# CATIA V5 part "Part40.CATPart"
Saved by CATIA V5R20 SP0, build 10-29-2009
Part number: FA 168700-1
Revision: ANY
Definition: UNKNOWN
Nomenclature: FA 168700-1
Source: Unknown
Bounding box of the stored display mesh (mm): x -3.804 to 3.804, y 0.28 to 2.5, z -4 to 4
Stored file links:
  C:\Users\Utente\Desktop\IO LAVORO\3D X SITO CF\CUMSA\3D files FA\FA 2007SF\Part40.CATPart

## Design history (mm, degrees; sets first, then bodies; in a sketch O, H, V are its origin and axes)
Body1 "Cortar-Extruir1" (main body)
  Solid1: solid without history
